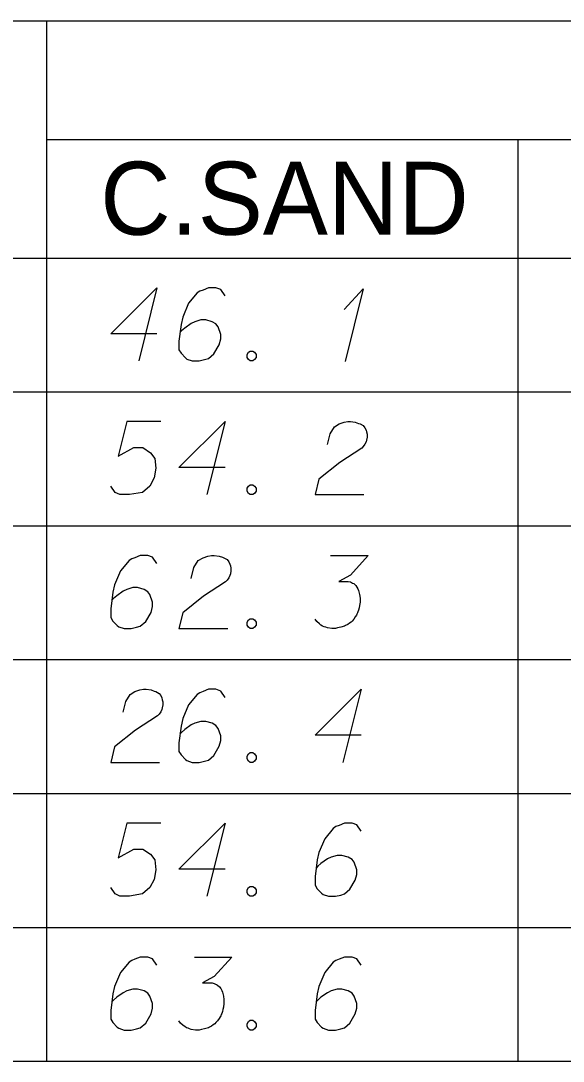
# Model space of a CAD drawing. Extents: x 2074207 to 2076812, y 516372 to 523312.
# Drawn here: x 2076524.4 to 2076560.1, y 516443.1 to 516511.5 of the extents above; entities that cross this region are included whole.
import ezdxf

# ---------------------------------------------------------------- set-up
doc = ezdxf.new("R2010")
doc.units = 0
for name, color, linetype in [('Prop DirtTable_ Soil Test Results - Outline (Major)', 7, 'Continuous'), ('Prop DirtTable_ Soil Test Results - Outline (Minor)', 7, 'Continuous'), ('Prop DirtTable_ Soil Test Results - Tx (Header - Small)', 7, 'Continuous'), ('Prop DirtTable_ Soil Test Results - Tx (Sample Data)', 7, 'Continuous')]:
    doc.layers.add(name, color=color, linetype=linetype)

msp = doc.modelspace()

# ---------------------------------------------------------------- linework, layer by layer
at = {"layer": 'Prop DirtTable_ Soil Test Results - Outline (Major)'}
for p, q in [((2076260.609, 516495.938), (2076811.903, 516495.938)), ((2076260.609, 516495.938), (2076811.903, 516495.938)), ((2076260.609, 516443.138), (2076811.903, 516443.138))]:
    msp.add_line(p, q, dxfattribs=at)
at = {"layer": 'Prop DirtTable_ Soil Test Results - Outline (Minor)'}
for p, q in [((2076260.609, 516511.538), (2076811.903, 516511.538)), ((2076526.074, 516511.538), (2076526.074, 516487.138)), ((2076526.074, 516503.738), (2076731.93, 516503.738)), ((2076557.094, 516503.738), (2076557.094, 516487.138)), ((2076260.609, 516487.138), (2076811.903, 516487.138)), ((2076260.609, 516487.138), (2076811.903, 516487.138)), ((2076526.074, 516487.138), (2076526.074, 516478.338)), ((2076557.094, 516487.138), (2076557.094, 516478.338)), ((2076260.609, 516478.338), (2076811.903, 516478.338)), ((2076260.609, 516478.338), (2076811.903, 516478.338)), ((2076526.074, 516478.338), (2076526.074, 516469.538)), ((2076557.094, 516478.338), (2076557.094, 516469.538)), ((2076260.609, 516469.538), (2076811.903, 516469.538)), ((2076260.609, 516469.538), (2076811.903, 516469.538)), ((2076526.074, 516469.538), (2076526.074, 516460.738)), ((2076557.094, 516469.538), (2076557.094, 516460.738)), ((2076260.609, 516460.738), (2076811.903, 516460.738)), ((2076260.609, 516460.738), (2076811.903, 516460.738)), ((2076526.074, 516460.738), (2076526.074, 516451.938)), ((2076557.094, 516460.738), (2076557.094, 516451.938)), ((2076260.609, 516451.938), (2076811.903, 516451.938)), ((2076260.609, 516451.938), (2076811.903, 516451.938)), ((2076526.074, 516451.938), (2076526.074, 516443.138)), ((2076557.094, 516451.938), (2076557.094, 516443.138)), ((2076260.609, 516443.138), (2076811.903, 516443.138))]:
    msp.add_line(p, q, dxfattribs=at)
at = {"layer": 'Prop DirtTable_ Soil Test Results - Tx (Sample Data)'}
for points in [[(2076533.349, 516490.963), (2076530.316, 516490.963), (2076533.349, 516493.986), (2076532.15, 516489.186)], [(2076537.829, 516493.457), (2076537.547, 516493.873), (2076537.23, 516493.986), (2076536.736, 516493.986), (2076536.383, 516493.835), (2076536.171, 516493.759), (2076535.995, 516493.646), (2076535.431, 516492.966), (2076535.043, 516492.059), (2076534.937, 516491.567), (2076534.796, 516490.471), (2076534.796, 516489.904), (2076534.937, 516489.678), (2076535.219, 516489.375), (2076535.325, 516489.3), (2076535.678, 516489.186), (2076536.136, 516489.186), (2076536.489, 516489.262), (2076536.736, 516489.337), (2076537.089, 516489.64), (2076537.441, 516490.244), (2076537.547, 516490.622), (2076537.547, 516490.925), (2076537.371, 516491.416), (2076537.23, 516491.605), (2076536.983, 516491.756), (2076536.559, 516491.87), (2076536.242, 516491.87), (2076535.854, 516491.756), (2076535.607, 516491.643), (2076535.184, 516491.341), (2076534.972, 516491.152), (2076534.866, 516491.038)], [(2076545.66, 516492.55), (2076546.93, 516493.911), (2076545.731, 516489.148)], [(2076539.487, 516489.829), (2076539.664, 516489.829), (2076539.769, 516489.753), (2076539.875, 516489.602), (2076539.875, 516489.413), (2076539.769, 516489.262), (2076539.664, 516489.186), (2076539.487, 516489.186), (2076539.381, 516489.262), (2076539.276, 516489.413), (2076539.276, 516489.602), (2076539.381, 516489.753), (2076539.487, 516489.829)], [(2076533.596, 516485.186), (2076531.374, 516485.186), (2076530.809, 516482.918), (2076531.832, 516483.485), (2076532.432, 516483.485), (2076532.926, 516483.145), (2076533.208, 516482.767), (2076533.279, 516482.125), (2076533.173, 516481.482), (2076532.891, 516480.953), (2076532.397, 516480.537), (2076531.55, 516480.386), (2076530.915, 516480.386), (2076530.598, 516480.537), (2076530.316, 516480.953)], [(2076537.829, 516482.163), (2076534.796, 516482.163), (2076537.829, 516485.186), (2076536.63, 516480.386)], [(2076544.567, 516483.674), (2076544.743, 516484.392), (2076545.026, 516484.846), (2076545.343, 516485.035), (2076545.66, 516485.148), (2076545.907, 516485.186), (2076546.084, 516485.186), (2076546.401, 516485.148), (2076546.613, 516485.073), (2076546.719, 516485.035), (2076546.93, 516484.922), (2076547.036, 516484.77), (2076547.107, 516484.619), (2076547.142, 516484.506), (2076547.177, 516484.355), (2076547.177, 516484.166), (2076547.142, 516483.977), (2076547.107, 516483.863), (2076547.036, 516483.712), (2076546.93, 516483.561), (2076546.825, 516483.448), (2076545.378, 516482.503), (2076544.003, 516481.407), (2076543.756, 516480.386), (2076546.966, 516480.386)], [(2076539.487, 516481.029), (2076539.664, 516481.029), (2076539.769, 516480.953), (2076539.875, 516480.802), (2076539.875, 516480.613), (2076539.769, 516480.462), (2076539.664, 516480.386), (2076539.487, 516480.386), (2076539.381, 516480.462), (2076539.276, 516480.613), (2076539.276, 516480.802), (2076539.381, 516480.953), (2076539.487, 516481.029)], [(2076533.349, 516475.857), (2076533.067, 516476.273), (2076532.75, 516476.386), (2076532.256, 516476.386), (2076531.903, 516476.235), (2076531.691, 516476.159), (2076531.515, 516476.046), (2076530.951, 516475.366), (2076530.563, 516474.459), (2076530.457, 516473.967), (2076530.316, 516472.871), (2076530.316, 516472.304), (2076530.457, 516472.078), (2076530.739, 516471.775), (2076530.845, 516471.7), (2076531.198, 516471.586), (2076531.656, 516471.586), (2076532.009, 516471.662), (2076532.256, 516471.737), (2076532.609, 516472.04), (2076532.961, 516472.644), (2076533.067, 516473.022), (2076533.067, 516473.325), (2076532.891, 516473.816), (2076532.75, 516474.005), (2076532.503, 516474.156), (2076532.079, 516474.27), (2076531.762, 516474.27), (2076531.374, 516474.156), (2076531.127, 516474.043), (2076530.704, 516473.741), (2076530.492, 516473.552), (2076530.386, 516473.438)], [(2076535.607, 516474.874), (2076535.783, 516475.592), (2076536.066, 516476.046), (2076536.383, 516476.235), (2076536.7, 516476.348), (2076536.947, 516476.386), (2076537.124, 516476.386), (2076537.441, 516476.348), (2076537.653, 516476.273), (2076537.759, 516476.235), (2076537.97, 516476.122), (2076538.076, 516475.97), (2076538.147, 516475.819), (2076538.182, 516475.706), (2076538.217, 516475.555), (2076538.217, 516475.366), (2076538.182, 516475.177), (2076538.147, 516475.063), (2076538.076, 516474.912), (2076537.97, 516474.761), (2076537.865, 516474.648), (2076536.418, 516473.703), (2076535.043, 516472.607), (2076534.796, 516471.586), (2076538.006, 516471.586)], [(2076544.779, 516476.386), (2076547.248, 516476.386), (2076546.084, 516475.101), (2076545.308, 516474.685), (2076545.943, 516474.685), (2076546.084, 516474.648), (2076546.154, 516474.61), (2076546.225, 516474.572), (2076546.295, 516474.534), (2076546.437, 516474.421), (2076546.507, 516474.307), (2076546.578, 516474.194), (2076546.613, 516474.081), (2076546.683, 516473.816), (2076546.719, 516473.589), (2076546.719, 516473.476), (2076546.719, 516473.325), (2076546.683, 516473.098), (2076546.648, 516472.947), (2076546.613, 516472.796), (2076546.578, 516472.682), (2076546.542, 516472.607), (2076546.507, 516472.531), (2076546.472, 516472.455), (2076546.401, 516472.342), (2076546.295, 516472.191), (2076546.19, 516472.078), (2076546.119, 516472.002), (2076546.013, 516471.926), (2076545.907, 516471.851), (2076545.766, 516471.775), (2076545.696, 516471.737), (2076545.449, 516471.662), (2076545.237, 516471.624), (2076545.096, 516471.586), (2076544.849, 516471.586), (2076544.567, 516471.624), (2076544.461, 516471.662), (2076544.355, 516471.7), (2076544.249, 516471.737), (2076544.144, 516471.813), (2076544.038, 516471.889), (2076543.861, 516472.04), (2076543.756, 516472.191)], [(2076539.487, 516472.229), (2076539.664, 516472.229), (2076539.769, 516472.153), (2076539.875, 516472.002), (2076539.875, 516471.813), (2076539.769, 516471.662), (2076539.664, 516471.586), (2076539.487, 516471.586), (2076539.381, 516471.662), (2076539.276, 516471.813), (2076539.276, 516472.002), (2076539.381, 516472.153), (2076539.487, 516472.229)], [(2076531.127, 516466.074), (2076531.303, 516466.792), (2076531.586, 516467.246), (2076531.903, 516467.435), (2076532.22, 516467.548), (2076532.467, 516467.586), (2076532.644, 516467.586), (2076532.961, 516467.548), (2076533.173, 516467.473), (2076533.279, 516467.435), (2076533.49, 516467.322), (2076533.596, 516467.17), (2076533.667, 516467.019), (2076533.702, 516466.906), (2076533.737, 516466.755), (2076533.737, 516466.566), (2076533.702, 516466.377), (2076533.667, 516466.263), (2076533.596, 516466.112), (2076533.49, 516465.961), (2076533.385, 516465.848), (2076531.938, 516464.903), (2076530.563, 516463.807), (2076530.316, 516462.786), (2076533.526, 516462.786)], [(2076537.829, 516467.057), (2076537.547, 516467.473), (2076537.23, 516467.586), (2076536.736, 516467.586), (2076536.383, 516467.435), (2076536.171, 516467.359), (2076535.995, 516467.246), (2076535.431, 516466.566), (2076535.043, 516465.659), (2076534.937, 516465.167), (2076534.796, 516464.071), (2076534.796, 516463.504), (2076534.937, 516463.278), (2076535.219, 516462.975), (2076535.325, 516462.9), (2076535.678, 516462.786), (2076536.136, 516462.786), (2076536.489, 516462.862), (2076536.736, 516462.937), (2076537.089, 516463.24), (2076537.441, 516463.844), (2076537.547, 516464.222), (2076537.547, 516464.525), (2076537.371, 516465.016), (2076537.23, 516465.205), (2076536.983, 516465.356), (2076536.559, 516465.47), (2076536.242, 516465.47), (2076535.854, 516465.356), (2076535.607, 516465.243), (2076535.184, 516464.941), (2076534.972, 516464.752), (2076534.866, 516464.638)], [(2076546.789, 516464.563), (2076543.756, 516464.563), (2076546.789, 516467.586), (2076545.59, 516462.786)], [(2076539.487, 516463.429), (2076539.664, 516463.429), (2076539.769, 516463.353), (2076539.875, 516463.202), (2076539.875, 516463.013), (2076539.769, 516462.862), (2076539.664, 516462.786), (2076539.487, 516462.786), (2076539.381, 516462.862), (2076539.276, 516463.013), (2076539.276, 516463.202), (2076539.381, 516463.353), (2076539.487, 516463.429)], [(2076533.596, 516458.786), (2076531.374, 516458.786), (2076530.809, 516456.518), (2076531.832, 516457.085), (2076532.432, 516457.085), (2076532.926, 516456.745), (2076533.208, 516456.367), (2076533.279, 516455.725), (2076533.173, 516455.082), (2076532.891, 516454.553), (2076532.397, 516454.137), (2076531.55, 516453.986), (2076530.915, 516453.986), (2076530.598, 516454.137), (2076530.316, 516454.553)], [(2076537.829, 516455.763), (2076534.796, 516455.763), (2076537.829, 516458.786), (2076536.63, 516453.986)], [(2076546.789, 516458.257), (2076546.507, 516458.673), (2076546.19, 516458.786), (2076545.696, 516458.786), (2076545.343, 516458.635), (2076545.131, 516458.559), (2076544.955, 516458.446), (2076544.391, 516457.766), (2076544.003, 516456.859), (2076543.897, 516456.367), (2076543.756, 516455.271), (2076543.756, 516454.704), (2076543.897, 516454.478), (2076544.179, 516454.175), (2076544.285, 516454.1), (2076544.638, 516453.986), (2076545.096, 516453.986), (2076545.449, 516454.062), (2076545.696, 516454.137), (2076546.049, 516454.44), (2076546.401, 516455.044), (2076546.507, 516455.422), (2076546.507, 516455.725), (2076546.331, 516456.216), (2076546.19, 516456.405), (2076545.943, 516456.556), (2076545.519, 516456.67), (2076545.202, 516456.67), (2076544.814, 516456.556), (2076544.567, 516456.443), (2076544.144, 516456.141), (2076543.932, 516455.952), (2076543.826, 516455.838)], [(2076539.487, 516454.629), (2076539.664, 516454.629), (2076539.769, 516454.553), (2076539.875, 516454.402), (2076539.875, 516454.213), (2076539.769, 516454.062), (2076539.664, 516453.986), (2076539.487, 516453.986), (2076539.381, 516454.062), (2076539.276, 516454.213), (2076539.276, 516454.402), (2076539.381, 516454.553), (2076539.487, 516454.629)], [(2076533.349, 516449.457), (2076533.067, 516449.873), (2076532.75, 516449.986), (2076532.256, 516449.986), (2076531.903, 516449.835), (2076531.691, 516449.759), (2076531.515, 516449.646), (2076530.951, 516448.966), (2076530.563, 516448.059), (2076530.457, 516447.567), (2076530.316, 516446.471), (2076530.316, 516445.904), (2076530.457, 516445.678), (2076530.739, 516445.375), (2076530.845, 516445.3), (2076531.198, 516445.186), (2076531.656, 516445.186), (2076532.009, 516445.262), (2076532.256, 516445.337), (2076532.609, 516445.64), (2076532.961, 516446.244), (2076533.067, 516446.622), (2076533.067, 516446.925), (2076532.891, 516447.416), (2076532.75, 516447.605), (2076532.503, 516447.756), (2076532.079, 516447.87), (2076531.762, 516447.87), (2076531.374, 516447.756), (2076531.127, 516447.643), (2076530.704, 516447.341), (2076530.492, 516447.152), (2076530.386, 516447.038)], [(2076535.819, 516449.986), (2076538.288, 516449.986), (2076537.124, 516448.701), (2076536.348, 516448.285), (2076536.983, 516448.285), (2076537.124, 516448.248), (2076537.194, 516448.21), (2076537.265, 516448.172), (2076537.335, 516448.134), (2076537.477, 516448.021), (2076537.547, 516447.907), (2076537.618, 516447.794), (2076537.653, 516447.681), (2076537.723, 516447.416), (2076537.759, 516447.189), (2076537.759, 516447.076), (2076537.759, 516446.925), (2076537.723, 516446.698), (2076537.688, 516446.547), (2076537.653, 516446.396), (2076537.618, 516446.282), (2076537.582, 516446.207), (2076537.547, 516446.131), (2076537.512, 516446.055), (2076537.441, 516445.942), (2076537.335, 516445.791), (2076537.23, 516445.678), (2076537.159, 516445.602), (2076537.053, 516445.526), (2076536.947, 516445.451), (2076536.806, 516445.375), (2076536.736, 516445.337), (2076536.489, 516445.262), (2076536.277, 516445.224), (2076536.136, 516445.186), (2076535.889, 516445.186), (2076535.607, 516445.224), (2076535.501, 516445.262), (2076535.395, 516445.3), (2076535.289, 516445.337), (2076535.184, 516445.413), (2076535.078, 516445.489), (2076534.901, 516445.64), (2076534.796, 516445.791)], [(2076546.789, 516449.457), (2076546.507, 516449.873), (2076546.19, 516449.986), (2076545.696, 516449.986), (2076545.343, 516449.835), (2076545.131, 516449.759), (2076544.955, 516449.646), (2076544.391, 516448.966), (2076544.003, 516448.059), (2076543.897, 516447.567), (2076543.756, 516446.471), (2076543.756, 516445.904), (2076543.897, 516445.678), (2076544.179, 516445.375), (2076544.285, 516445.3), (2076544.638, 516445.186), (2076545.096, 516445.186), (2076545.449, 516445.262), (2076545.696, 516445.337), (2076546.049, 516445.64), (2076546.401, 516446.244), (2076546.507, 516446.622), (2076546.507, 516446.925), (2076546.331, 516447.416), (2076546.19, 516447.605), (2076545.943, 516447.756), (2076545.519, 516447.87), (2076545.202, 516447.87), (2076544.814, 516447.756), (2076544.567, 516447.643), (2076544.144, 516447.341), (2076543.932, 516447.152), (2076543.826, 516447.038)], [(2076539.487, 516445.829), (2076539.664, 516445.829), (2076539.769, 516445.753), (2076539.875, 516445.602), (2076539.875, 516445.413), (2076539.769, 516445.262), (2076539.664, 516445.186), (2076539.487, 516445.186), (2076539.381, 516445.262), (2076539.276, 516445.413), (2076539.276, 516445.602), (2076539.381, 516445.753), (2076539.487, 516445.829)]]:
    msp.add_lwpolyline(points, dxfattribs=at)

# ---------------------------------------------------------------- texts
at = {"layer": 'Prop DirtTable_ Soil Test Results - Tx (Header - Small)'}
msp.add_text('C.SAND', height=4.8, dxfattribs=at).set_placement((2076529.618, 516497.473))

doc.saveas('drawing.dxf')
